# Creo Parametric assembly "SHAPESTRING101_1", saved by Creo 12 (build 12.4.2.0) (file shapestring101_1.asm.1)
Units: Custom; MM, KILOGRAM, SECS

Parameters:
  PTC_WM_ITERATION = "0"
  PTC_WM_VERSION = "-.0"
  PTC_WM_LIFECYCLE_STATE = "In Work"
  PTC_WM_LIFECYCLE = "MO_CADDocument"
  PTC_WM_CREATED_BY = "Maximilian Roepper (Z0017RMS: MO)"
  PTC_WM_CREATED_ON = "18-Sep-26 11:36:42 AM"
  PTC_WM_MODIFIED_BY = "Maximilian Roepper (Z0017RMS: MO)"
  PTC_WM_MODIFIED_ON = "18-Sep-26 11:36:46 AM"
  PDMLINKNUMBER = "PDM000071455045"
  PTC_WM_NAME = "shapestring101_1.asm"
  PTC_WM_NUMBER = "PDM000071455045"

Other parameters: WEIGHT, WEIGHT_FACTOR, WEIGHT_ADD, MC_ERRORS, SUPPLIER, ISPOSITIONINGASSEMBLY

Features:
  1. coordinate system
  2. imported feature
  3. component "SHAPESTRING099_1"
  4. component "SHAPESTRING100_1"

Other named items: DRW_VIEW_ORG, ROUGH-GROB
